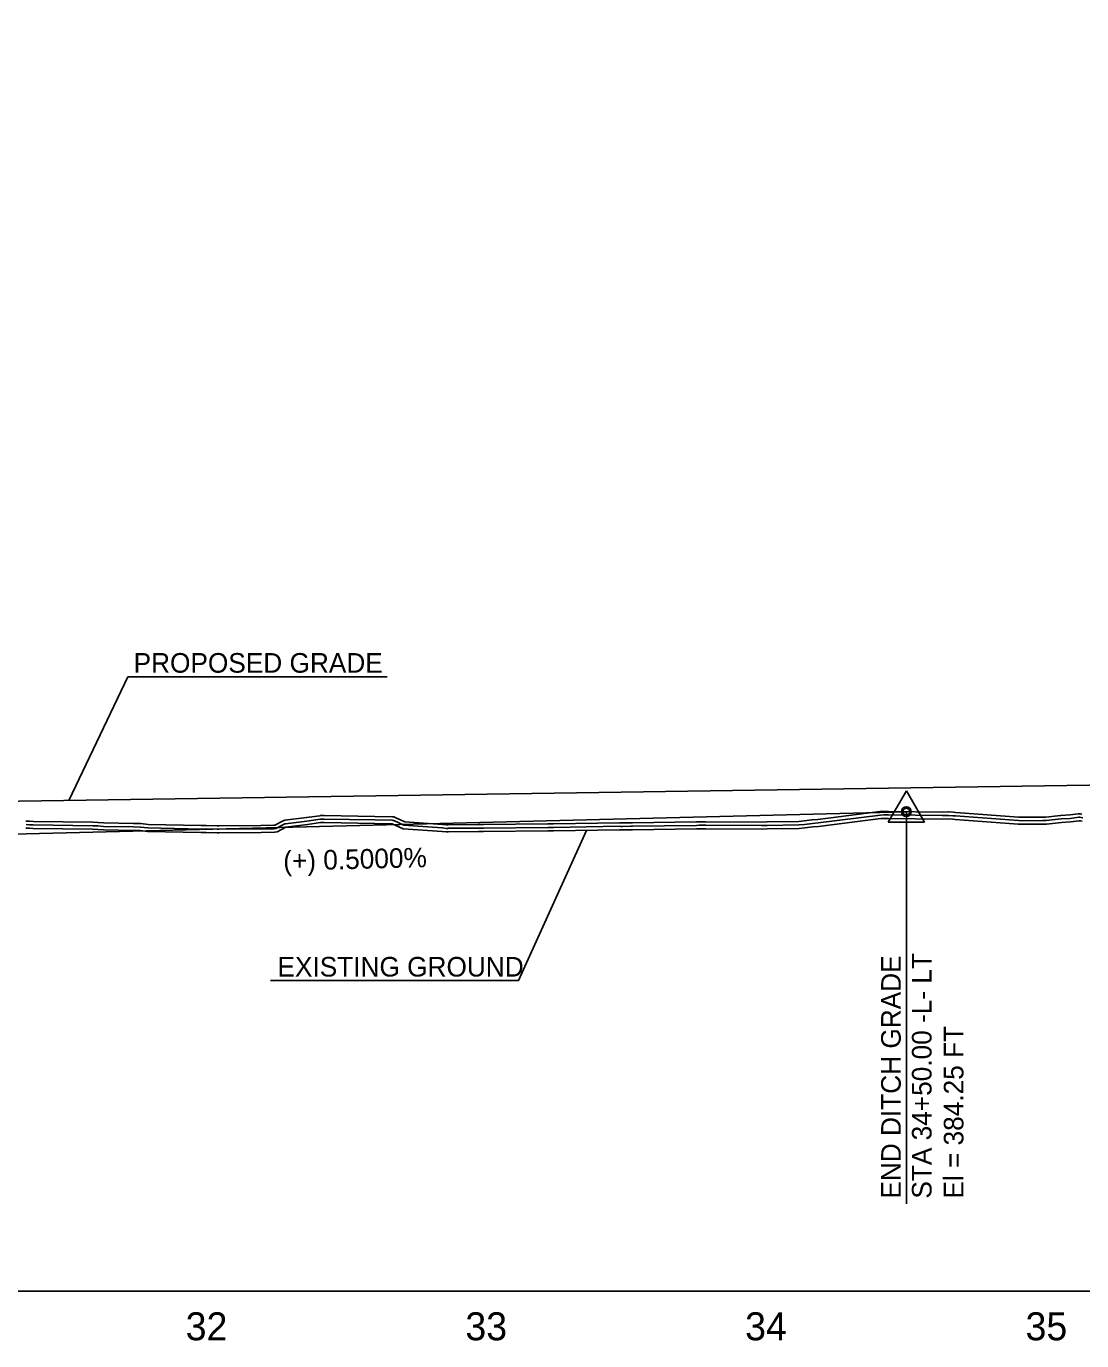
# Model space of a CAD drawing. Extents: x 1625686 to 1640492, y 1161393 to 1175642.
# Drawn here: x 1632340.2 to 1632716.9, y 1174893.1 to 1175362.5 of the extents above; entities that cross this region are included whole.
import ezdxf

# ---------------------------------------------------------------- set-up
doc = ezdxf.new("R2010")
doc.units = 0
for name, color, linetype in [('Exist Profile Cell', 7, 'Continuous'), ('Exist Vertical Profile Ground Line', 7, 'Continuous'), ('Exist Vertical Profile Horizontal Axis Label Major', 7, 'Continuous'), ('Prop Vertical Profile Ditch Grade Left', 7, 'Continuous'), ('Prop Vertical Profile Ditch Grade Left Label', 7, 'Continuous'), ('Prop Vertical Profile Grade', 7, 'Continuous'), ('Prop VPI Ditch Grade Left Label', 7, 'Continuous'), ('Prop VPI Label', 7, 'Continuous'), ('Scratch_Level_1', 7, 'Continuous'), ('Scratch_Level_3', 7, 'Continuous'), ('Scratch_Level_5', 7, 'Continuous')]:
    doc.layers.add(name, color=color, linetype=linetype)

msp = doc.modelspace()

# ---------------------------------------------------------------- linework, layer by layer
at = {"layer": 'Exist Profile Cell'}
msp.add_line((1630204.31, 1174910.79), (1634670.63, 1174910.79), dxfattribs=at)
at = {"layer": 'Exist Vertical Profile Ground Line'}
msp.add_lwpolyline([(1632340.04, 1175076.18), (1632341.29, 1175076.11), (1632342.68, 1175076.09), (1632363.86, 1175075.75), (1632365.67, 1175075.7), (1632367.69, 1175075.54), (1632378.47, 1175075.35), (1632380.82, 1175075.28), (1632383.49, 1175074.99), (1632402.56, 1175074.57), (1632404.35, 1175074.63), (1632408.28, 1175074.54), (1632408.96, 1175074.52), (1632423.97, 1175074.63), (1632428.81, 1175074.72), (1632429.71, 1175074.88), (1632432.81, 1175076.49), (1632440.51, 1175077.45), (1632445.26, 1175078.13), (1632446.46, 1175078.13), (1632464.61, 1175077.84), (1632470.82, 1175077.73), (1632474.65, 1175075.95), (1632488.58, 1175074.99), (1632490.04, 1175074.79), (1632490.81, 1175074.85), (1632501.54, 1175074.94), (1632502.43, 1175074.95), (1632503.38, 1175074.95), (1632526.37, 1175075.17), (1632526.99, 1175075.18), (1632527.65, 1175075.19), (1632528.32, 1175075.16), (1632551.91, 1175075.58), (1632552.4, 1175075.55), (1632552.93, 1175075.54), (1632555.95, 1175075.57), (1632556.57, 1175075.6), (1632579.46, 1175075.86), (1632580.44, 1175075.93), (1632581.51, 1175075.96), (1632582.69, 1175075.94), (1632602.67, 1175075.82), (1632604.62, 1175075.88), (1632616.06, 1175076.05), (1632618.13, 1175076.27), (1632620.92, 1175076.61), (1632622.95, 1175076.76), (1632645.19, 1175079.58), (1632646.31, 1175079.65), (1632647.92, 1175079.65), (1632667.14, 1175079.37), (1632669.32, 1175079.46), (1632670.85, 1175079.34), (1632671.74, 1175079.28), (1632694.23, 1175077.6), (1632695.26, 1175077.56), (1632703.05, 1175077.59), (1632704.29, 1175077.59), (1632709.66, 1175078.2), (1632712.87, 1175078.39), (1632716.03, 1175078.82), (1632716.46, 1175078.74), (1632717.1, 1175078.61)], dxfattribs=at)
at = {"layer": 'Prop Vertical Profile Ditch Grade Left'}
msp.add_lwpolyline([(1632138.55, 1175050.09), (1632254.31, 1175072.04), (1632654.31, 1175082.04)], dxfattribs=at)
at = {"layer": 'Prop Vertical Profile Grade'}
msp.add_line((1632304.31, 1175085.25), (1632929.31, 1175094.7), dxfattribs=at)
at = {"layer": 'Prop VPI Ditch Grade Left Label'}
for p, q in [((1632654.31, 1175089.52), (1632647.86, 1175078.32)), ((1632654.31, 1175089.52), (1632660.81, 1175078.32)), ((1632654.31, 1175082.04), (1632654.31, 1174951.57)), ((1632647.86, 1175078.32), (1632660.81, 1175078.32)), ((1632654.31, 1175072.54), (1632654.31, 1174942.07))]:
    msp.add_line(p, q, dxfattribs=at)
for radius in [1.75, 1.2]:
    msp.add_circle((1632654.31, 1175082.04), radius, dxfattribs=at)
at = {"layer": 'Prop VPI Label'}
for p, q in [((1632376.44, 1175130.23), (1632355.41, 1175086.03)), ((1632468.99, 1175130.23), (1632376.44, 1175130.23)), ((1632515.93, 1175021.72), (1632540.12, 1175075.37)), ((1632515.93, 1175021.72), (1632427.32, 1175021.72))]:
    msp.add_line(p, q, dxfattribs=at)
at = {"layer": 'Scratch_Level_1'}
for p, q in [((1632445.26, 1175080.63), (1632446.46, 1175080.63)), ((1632445.26, 1175079.38), (1632446.46, 1175079.38)), ((1632446.48, 1175079.38), (1632464.63, 1175079.09)), ((1632446.5, 1175080.63), (1632464.65, 1175080.34)), ((1632464.63, 1175079.09), (1632470.84, 1175078.98)), ((1632464.65, 1175080.34), (1632470.86, 1175080.23)), ((1632645.04, 1175082.08), (1632646.16, 1175082.15)), ((1632645.11, 1175080.83), (1632646.24, 1175080.9)), ((1632646.32, 1175082.15), (1632647.93, 1175082.15)), ((1632646.32, 1175080.9), (1632647.93, 1175080.9)), ((1632716.26, 1175080.05), (1632716.68, 1175079.97)), ((1632716.48, 1175081.28), (1632716.9, 1175081.2)), ((1632716.71, 1175079.97), (1632717.35, 1175079.84)), ((1632342.7, 1175077.34), (1632363.88, 1175077)), ((1632342.72, 1175078.59), (1632363.9, 1175078.25)), ((1632363.9, 1175077), (1632365.7, 1175076.94)), ((1632363.94, 1175078.25), (1632365.74, 1175078.19)), ((1632378.5, 1175076.6), (1632380.86, 1175076.53)), ((1632378.54, 1175077.85), (1632380.9, 1175077.78)), ((1632490.79, 1175077.35), (1632501.51, 1175077.44)), ((1632490.8, 1175076.1), (1632501.53, 1175076.19)), ((1632501.52, 1175077.44), (1632502.41, 1175077.45)), ((1632501.53, 1175076.19), (1632502.42, 1175076.2)), ((1632580.38, 1175078.43), (1632581.45, 1175078.46)), ((1632580.41, 1175077.18), (1632581.48, 1175077.21))]:
    msp.add_line(p, q, dxfattribs=at)
for points in [[(1632340.19, 1175078.68), (1632341.38, 1175078.6), (1632342.71, 1175078.59)], [(1632404.4, 1175077.13), (1632408.33, 1175077.04), (1632408.98, 1175077.02), (1632423.93, 1175077.13), (1632428.57, 1175077.22), (1632428.9, 1175077.27), (1632431.66, 1175078.71)], [(1632432.5, 1175078.97), (1632440.18, 1175079.93), (1632444.91, 1175080.6)], [(1632432.66, 1175077.73), (1632440.34, 1175078.69), (1632445.08, 1175079.37)], [(1632471.35, 1175078.87), (1632474.96, 1175077.18), (1632488.67, 1175076.23)], [(1632471.87, 1175080), (1632475.28, 1175078.41), (1632488.76, 1175077.48)], [(1632604.59, 1175078.38), (1632615.91, 1175078.55), (1632617.85, 1175078.75), (1632620.61, 1175079.09)], [(1632620.74, 1175079.11), (1632622.7, 1175079.25), (1632644.87, 1175082.06)], [(1632620.83, 1175077.86), (1632622.83, 1175078), (1632645.03, 1175080.82)], [(1632647.94, 1175080.9), (1632667.12, 1175080.62), (1632669.27, 1175080.71)], [(1632647.96, 1175082.15), (1632667.1, 1175081.87), (1632669.21, 1175081.95)], [(1632669.41, 1175080.7), (1632670.94, 1175080.59), (1632671.83, 1175080.53)], [(1632669.51, 1175081.95), (1632671.03, 1175081.83), (1632671.91, 1175081.77)], [(1632671.83, 1175080.53), (1632694.29, 1175078.85), (1632695.28, 1175078.81), (1632703.05, 1175078.84)], [(1632671.93, 1175081.77), (1632694.36, 1175080.09), (1632695.3, 1175080.06), (1632703.04, 1175080.09)], [(1632703.05, 1175078.84), (1632704.22, 1175078.84), (1632709.52, 1175079.44)], [(1632703.06, 1175080.09), (1632704.15, 1175080.09), (1632709.38, 1175080.68)], [(1632709.51, 1175080.69), (1632712.62, 1175080.88), (1632715.7, 1175081.3)], [(1632709.58, 1175079.44), (1632712.74, 1175079.64), (1632715.87, 1175080.06)], [(1632340.11, 1175077.43), (1632341.34, 1175077.36), (1632342.7, 1175077.34)], [(1632365.76, 1175076.94), (1632367.75, 1175076.79), (1632378.49, 1175076.6)], [(1632365.86, 1175078.19), (1632367.81, 1175078.04), (1632378.51, 1175077.85)], [(1632380.96, 1175076.52), (1632383.57, 1175076.24), (1632402.55, 1175075.82), (1632404.31, 1175075.88)], [(1632381.09, 1175077.76), (1632383.65, 1175077.49), (1632402.55, 1175077.08), (1632404.27, 1175077.13)], [(1632404.38, 1175075.88), (1632408.3, 1175075.79), (1632408.97, 1175075.77), (1632423.95, 1175075.88), (1632428.69, 1175075.97), (1632429.3, 1175076.08), (1632432.24, 1175077.6)], [(1632488.75, 1175076.23), (1632490.08, 1175076.05), (1632490.72, 1175076.09)], [(1632488.91, 1175077.46), (1632490.12, 1175077.3), (1632490.64, 1175077.34)], [(1632502.42, 1175077.45), (1632503.37, 1175077.45), (1632526.34, 1175077.67)], [(1632502.42, 1175076.2), (1632503.38, 1175076.2), (1632526.35, 1175076.42)], [(1632526.34, 1175077.67), (1632526.96, 1175077.68), (1632527.61, 1175077.69)], [(1632526.35, 1175076.42), (1632526.98, 1175076.43), (1632527.63, 1175076.44)], [(1632527.7, 1175076.44), (1632528.33, 1175076.41), (1632551.89, 1175076.82)], [(1632527.75, 1175077.69), (1632528.35, 1175077.66), (1632551.87, 1175078.07)], [(1632551.98, 1175076.82), (1632552.44, 1175076.8), (1632552.94, 1175076.79), (1632555.92, 1175076.82), (1632556.52, 1175076.85)], [(1632552.05, 1175078.07), (1632552.48, 1175078.05), (1632552.94, 1175078.04), (1632555.88, 1175078.07), (1632556.46, 1175078.1)], [(1632556.55, 1175078.1), (1632579.36, 1175078.36), (1632580.26, 1175078.43)], [(1632556.56, 1175076.85), (1632579.41, 1175077.11), (1632580.35, 1175077.18)], [(1632581.53, 1175077.21), (1632582.7, 1175077.19), (1632602.65, 1175077.07), (1632604.58, 1175077.13)], [(1632581.55, 1175078.46), (1632582.72, 1175078.44), (1632602.64, 1175078.32), (1632604.54, 1175078.38)], [(1632604.61, 1175077.13), (1632615.98, 1175077.3), (1632617.99, 1175077.51), (1632620.76, 1175077.85)]]:
    msp.add_lwpolyline(points, dxfattribs=at)
for centre, radius, start, end in [((1632340.04, 1175076.18), 2.5, 86.5505, 90.2705), ((1632432.81, 1175076.49), 2.5, 97.1007, 117.4547), ((1632445.26, 1175078.13), 2.5, 90.0597, 98.1475), ((1632445.26, 1175078.13), 1.25, 90.0597, 98.1475), ((1632446.46, 1175078.13), 2.5, 89.0741, 90.0597), ((1632446.46, 1175078.13), 1.25, 89.0741, 90.0597), ((1632464.61, 1175077.84), 1.25, 89.0456, 89.0741), ((1632464.61, 1175077.84), 2.5, 89.0456, 89.0741), ((1632470.82, 1175077.73), 1.25, 65.0428, 89.0456), ((1632470.82, 1175077.73), 2.5, 65.0428, 89.0456), ((1632620.92, 1175076.61), 2.5, 94.1076, 97.1102), ((1632645.19, 1175079.58), 2.5, 93.3682, 97.2439), ((1632645.19, 1175079.58), 1.25, 93.3682, 97.2439), ((1632646.31, 1175079.65), 2.5, 89.82, 93.3682), ((1632646.31, 1175079.65), 1.25, 89.82, 93.3682), ((1632647.92, 1175079.65), 2.5, 89.1637, 89.82), ((1632647.92, 1175079.65), 1.25, 89.1637, 89.82), ((1632669.32, 1175079.46), 2.5, 85.684, 92.3858), ((1632669.32, 1175079.46), 1.25, 85.684, 92.3858), ((1632671.74, 1175079.28), 1.25, 85.7228, 85.9921), ((1632671.74, 1175079.28), 2.5, 85.7228, 85.9921), ((1632703.05, 1175077.59), 2.5, 89.8781, 90.191), ((1632703.05, 1175077.59), 1.25, 89.8781, 90.191), ((1632709.66, 1175078.2), 2.5, 93.5415, 96.4837), ((1632709.66, 1175078.2), 1.25, 93.5415, 96.4837), ((1632716.03, 1175078.82), 2.5, 79.7394, 97.6368), ((1632716.03, 1175078.82), 1.25, 79.7394, 97.6368), ((1632716.46, 1175078.74), 1.25, 78.3717, 79.7394), ((1632716.46, 1175078.74), 2.5, 78.3717, 79.7394), ((1632342.68, 1175076.09), 1.25, 89.0852, 89.2489), ((1632342.68, 1175076.09), 2.5, 89.0852, 89.2489), ((1632363.86, 1175075.75), 1.25, 88.2757, 89.0852), ((1632363.86, 1175075.75), 2.5, 88.2757, 89.0852), ((1632365.67, 1175075.7), 1.25, 85.595, 88.2757), ((1632365.67, 1175075.7), 2.5, 85.595, 88.2757), ((1632378.47, 1175075.35), 1.25, 88.2262, 88.9926), ((1632378.47, 1175075.35), 2.5, 88.2262, 88.9926), ((1632380.82, 1175075.28), 1.25, 83.8473, 88.2262), ((1632380.82, 1175075.28), 2.5, 83.8473, 88.2262), ((1632404.35, 1175074.63), 2.5, 88.6534, 91.7691), ((1632404.35, 1175074.63), 1.25, 88.6534, 91.7691), ((1632432.81, 1175076.49), 1.25, 97.1007, 117.4547), ((1632488.58, 1175074.99), 1.25, 82.4355, 86.0326), ((1632488.58, 1175074.99), 2.5, 82.4355, 86.0326), ((1632490.81, 1175074.85), 2.5, 90.5234, 93.9564), ((1632490.81, 1175074.85), 1.25, 90.5234, 93.9564), ((1632501.54, 1175074.94), 2.5, 90.4136, 90.5234), ((1632501.54, 1175074.94), 1.25, 90.4136, 90.5234), ((1632502.43, 1175074.95), 2.5, 90.2441, 90.4136), ((1632502.43, 1175074.95), 1.25, 90.2441, 90.4136), ((1632526.37, 1175075.17), 2.5, 90.5145, 90.5423), ((1632526.37, 1175075.17), 1.25, 90.5145, 90.5423), ((1632527.65, 1175075.19), 2.5, 87.6029, 90.8764), ((1632527.65, 1175075.19), 1.25, 87.6029, 90.8764), ((1632551.91, 1175075.58), 2.5, 86.9887, 91.009), ((1632551.91, 1175075.58), 1.25, 86.9887, 91.009), ((1632556.57, 1175075.6), 2.5, 90.6594, 92.6721), ((1632556.57, 1175075.6), 1.25, 90.6594, 92.6721), ((1632580.44, 1175075.93), 2.5, 91.2404, 94.1057), ((1632580.44, 1175075.93), 1.25, 91.2404, 94.1057), ((1632581.51, 1175075.96), 2.5, 89.005, 91.2404), ((1632581.51, 1175075.96), 1.25, 89.005, 91.2404), ((1632604.62, 1175075.88), 2.5, 90.8459, 91.875), ((1632604.62, 1175075.88), 1.25, 90.8459, 91.875), ((1632620.92, 1175076.61), 1.25, 94.1076, 97.1102)]:
    msp.add_arc(centre, radius, start, end, dxfattribs=at)
at = {"layer": 'Scratch_Level_3'}
msp.add_lwpolyline([(1630204.31, 1174910.79), (1634341.72, 1174910.79), (1634341.72, 1175362.47)], dxfattribs=at)
at = {"layer": 'Scratch_Level_5'}
msp.add_lwpolyline([(1632340.04, 1175076.18), (1632341.29, 1175076.11), (1632342.68, 1175076.09), (1632363.86, 1175075.75), (1632365.67, 1175075.7), (1632367.69, 1175075.54), (1632378.47, 1175075.35), (1632380.82, 1175075.28), (1632383.49, 1175074.99), (1632402.56, 1175074.57), (1632404.35, 1175074.63), (1632408.28, 1175074.54), (1632408.96, 1175074.52), (1632423.97, 1175074.63), (1632428.81, 1175074.72), (1632429.71, 1175074.88), (1632432.81, 1175076.49), (1632440.51, 1175077.45), (1632445.26, 1175078.13), (1632446.46, 1175078.13), (1632464.61, 1175077.84), (1632470.82, 1175077.73), (1632474.65, 1175075.95), (1632488.58, 1175074.99), (1632490.04, 1175074.79), (1632490.81, 1175074.85), (1632501.54, 1175074.94), (1632502.43, 1175074.95), (1632503.38, 1175074.95), (1632526.37, 1175075.17), (1632526.99, 1175075.18), (1632527.65, 1175075.19), (1632528.32, 1175075.16), (1632551.91, 1175075.58), (1632552.4, 1175075.55), (1632552.93, 1175075.54), (1632555.95, 1175075.57), (1632556.57, 1175075.6), (1632579.46, 1175075.86), (1632580.44, 1175075.93), (1632581.51, 1175075.96), (1632582.69, 1175075.94), (1632602.67, 1175075.82), (1632604.62, 1175075.88), (1632616.06, 1175076.05), (1632618.13, 1175076.27), (1632620.92, 1175076.61), (1632622.95, 1175076.76), (1632645.19, 1175079.58), (1632646.31, 1175079.65), (1632647.92, 1175079.65), (1632667.14, 1175079.37), (1632669.32, 1175079.46), (1632670.85, 1175079.34), (1632671.74, 1175079.28), (1632694.23, 1175077.6), (1632695.26, 1175077.56), (1632703.05, 1175077.59), (1632704.29, 1175077.59), (1632709.66, 1175078.2), (1632712.87, 1175078.39), (1632716.03, 1175078.82), (1632716.46, 1175078.74), (1632717.1, 1175078.61)], dxfattribs=at)

# ---------------------------------------------------------------- texts
at = {"layer": 'Exist Vertical Profile Horizontal Axis Label Major'}
for s, p in [('32', (1632397.09, 1174893.29)), ('33', (1632496.92, 1174893.29)), ('34', (1632596.77, 1174893.29)), ('35', (1632696.86, 1174893.29))]:
    msp.add_text(s, height=10, dxfattribs=at).set_placement(p)
at = {"layer": 'Prop Vertical Profile Ditch Grade Left Label'}
msp.add_text('(+) 0.5000%', height=7, rotation=1.4321, dxfattribs=at).set_placement((1632431.98, 1175060.96))
at = {"layer": 'Prop VPI Ditch Grade Left Label'}
for s, p in [('END DITCH GRADE', (1632652.31, 1174943.88)), ('STA 34+50.00 -L- LT', (1632663.31, 1174943.88)), ('El = 384.25 FT', (1632674.69, 1174943.88))]:
    msp.add_text(s, height=7, rotation=90, dxfattribs=at).set_placement(p)
at = {"layer": 'Prop VPI Label'}
for s, p in [('PROPOSED GRADE', (1632378.49, 1175131.67)), ('EXISTING GROUND', (1632429.84, 1175023.17))]:
    msp.add_text(s, height=7, dxfattribs=at).set_placement(p)

doc.saveas('drawing.dxf')
